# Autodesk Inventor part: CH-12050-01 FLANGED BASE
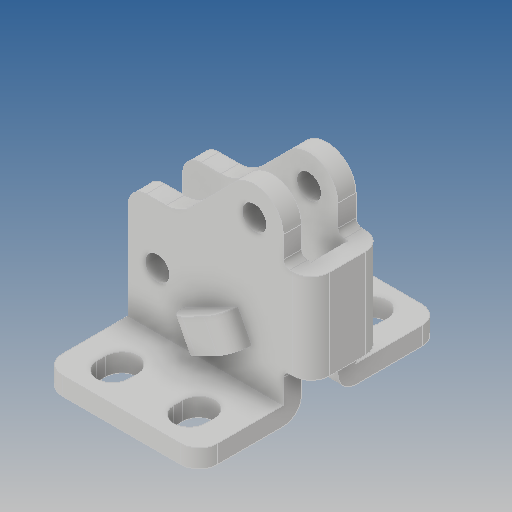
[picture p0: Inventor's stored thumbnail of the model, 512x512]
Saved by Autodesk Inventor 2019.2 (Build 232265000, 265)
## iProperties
Created: 2015-08
Part Number: CH-12050-01 FLANGED BASE
Material: Ogólny
Document SubType Name: Modeling
Designer: CADENGINEERING4
Density: 1 g/cm^3
Appearance: Domyślna
Author: CADENGINEERING4
Revision Number: ÈÎºÎ
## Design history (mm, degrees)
feature "Ô²½Ç5"
node "Bryła1"
